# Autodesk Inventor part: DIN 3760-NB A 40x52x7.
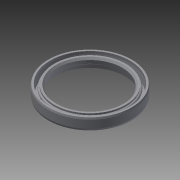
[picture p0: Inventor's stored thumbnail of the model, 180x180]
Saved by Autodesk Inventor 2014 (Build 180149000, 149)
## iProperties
Created: 2001-02
Part Number: DIN 3760-NB A 40x52x7.
Material: Delrin, Black
Description: Sealing A 40x52x7 DIN 3760-NB.
Document SubType Name: Modeling
Designer: Roman
Density: 1.425 g/cm^3
Appearance: Default
ProtocolID: P00020917135250765
Protocol: P00020917135250765<@PID>[View]<@EL>View=MODEL<@EL>Description=Parametric model<@EL>VISIBLED=1<@EL>Data=(setq _data (list "40x52x7" "40.00" "52.00" "7.00" "0.40"
Control State: 0
Master: False
Checked Out: False
Shininess: 20.0
Length Units: 11269
Angle Units: 11279
Time Units: 11290
Mass Units: 11283
Length Display Precision: 3
Angle Display Precision: 2
BOM1: Sealing
BOM2: A 40x52x7
BOM3: DIN 3760-NB
Density: 1.425
Volumn: 9.254323449797514
Area: 99.20977806041621
PropertySet Name: Model Information
Author: PaulN
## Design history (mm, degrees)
node "WorkPlane2"
node "Sketch1"
node "WorkPoint1"
node "WorkPlane3"
sketch "Sketch2"
  geometry: L1 (-26, 0)-(-24.6, 0); L2 (-26, -7)-(-26, 0); L3 (-21.714, -7)-(-26, -7); L4 (-21.234, -4.2)-(-21.714, -7); L5 (-20.377, -3.85)-(-21.234, -4.2); L6 (-20, -1.567)-(-20.377, -3.85); L7 (-20.857, -0.4)-(-20, -1.567); L8 (-22.069, -0.4)-(-20.857, -0.4); L9 (-22.069, -1.4)-(-22.069, -0.4); L10 (-22.069, -5.6)-(-22.069, -3.267); L11 (-24.138, -5.6)-(-22.069, -5.6); L12 (-24.6, -1.4)-(-24.138, -5.6); L13 (-24.6, 0)-(-24.6, -1.4); L14 (0, 16.309)-(0, -5.341); L15 (0, 16.309)-(0, -5.341); L16 (-31.2, 0)-(5.2, 0) reference; L17 (0, -11.662)-(0, 20.97) reference; A1 r 0.933 centre (-22.069, -2.333) between (-22.069, -1.4) and (-22.069, -3.267)
  constraints: 30 end point, 5 vertical, 4 horizontal, 2 collinear, 2 point on circle, 1 centre point, 1 horizontal alignment
  dimensions: "d2" = 7 distance of L2.start L1.start (= prf_b); "d4" = 1.4 vertical distance of L2.start L11.start (= 0.2 x prf_b); "d6" = 1 distance of L9.start L8.start (= 0.142857 x prf_b); "d8" = 2.33333 distance of L10.start L10.end (= 0.333333 x prf_b); "d10" = 1.4 distance of L1.start L1.end (= 0.2 x prf_b); "d12" = 1.4 distance of L1.end L12.start (= 0.2 x prf_b); "d14" = 4.28571 distance of L3.start L2.start (= 0.357143 x prf_dd - 0.357143 x prf_d); "d16" = 2.06897 distance of L11.start L10.start (= 0.172414 x prf_dd - 0.172414 x prf_d); "d18" = 2.06897 horizontal distance of L8.start L6.start (= 0.172414 x prf_dd - 0.172414 x prf_d); "d20" = 0 horizontal distance of A1.centre L9.start; "d22" = 0 horizontal distance of A1.centre L10.end; "d24" = 26 horizontal distance of L2.start L14.start (= 0.5 x prf_dd); "d26" = 2.8 vertical distance of L4.start L3.start (= 0.4 x prf_b); "d28" = 0.48 horizontal distance of L4.start L3.start (= 0.04 x prf_dd - 0.04 x prf_d); "d30" = 0.85714 horizontal distance of L7.start L6.start (= 0.0714286 x prf_dd - 0.0714286 x prf_d); "d32" = 1.16667 vertical distance of L7.start L6.start (= 0.166667 x prf_b); "d34" = 0.35 vertical distance of L5.start L4.start (= 0.05 x prf_b); "d36" = 0.85714 horizontal distance of L5.start L4.start (= 0.0714286 x prf_dd - 0.0714286 x prf_d); "msp_d43" = 40 diameter of L6.start L14 (= prf_d)
revolve "RevolutionFull1" sketch "Sketch2" stored, may be unused: angle "d37" = 360 deg
fillet "Fillet1" dims "d38" = 1.4 (= 0.2 x prf_b)
chamfer "Chamfer1" distance "d39" = 0.3 (= 0.025 x prf_dd - 0.025 x prf_d); stored, may be unused: second distance "d40" = 1.07692 (= 0.153846 x prf_b), angle "d46" = 45 deg
chamfer "Chamfer2" distance "d41" = 1.07692 (= 0.153846 x prf_b); stored, may be unused: second distance "d42" = 0.3 (= 0.025 x prf_dd - 0.025 x prf_d), angle "d47" = 45 deg
body "Solid1"
other parameters: "prf_dd" = 52 [user parameter; used in 9 equation terms], "prf_d" = 40 [user parameter; used in 9 equation terms], "prf_b" = 7 [user parameter; used in 13 equation terms], "d0" = -7 (computed from prf_b), "d1" = 8 (derived), "d3" = 1.6 (derived), "d5" = 1.14286 (derived), "d7" = 2.66667 (derived), "d9" = 1.6 (derived), "d11" = 1.6 (derived), "d13" = 7.14286 (derived), "d15" = 3.44828 (derived), "d17" = 3.44828 (derived), "d19" = 0 (derived), "d21" = 0 (derived), "d25" = 3.2 (derived), "d27" = 0.8 (derived), "d29" = 1.42857 (derived), "d31" = 1.33333 (derived), "d33" = 0.4 (derived), "d35" = 1.42857 (derived), "d45" = 0
